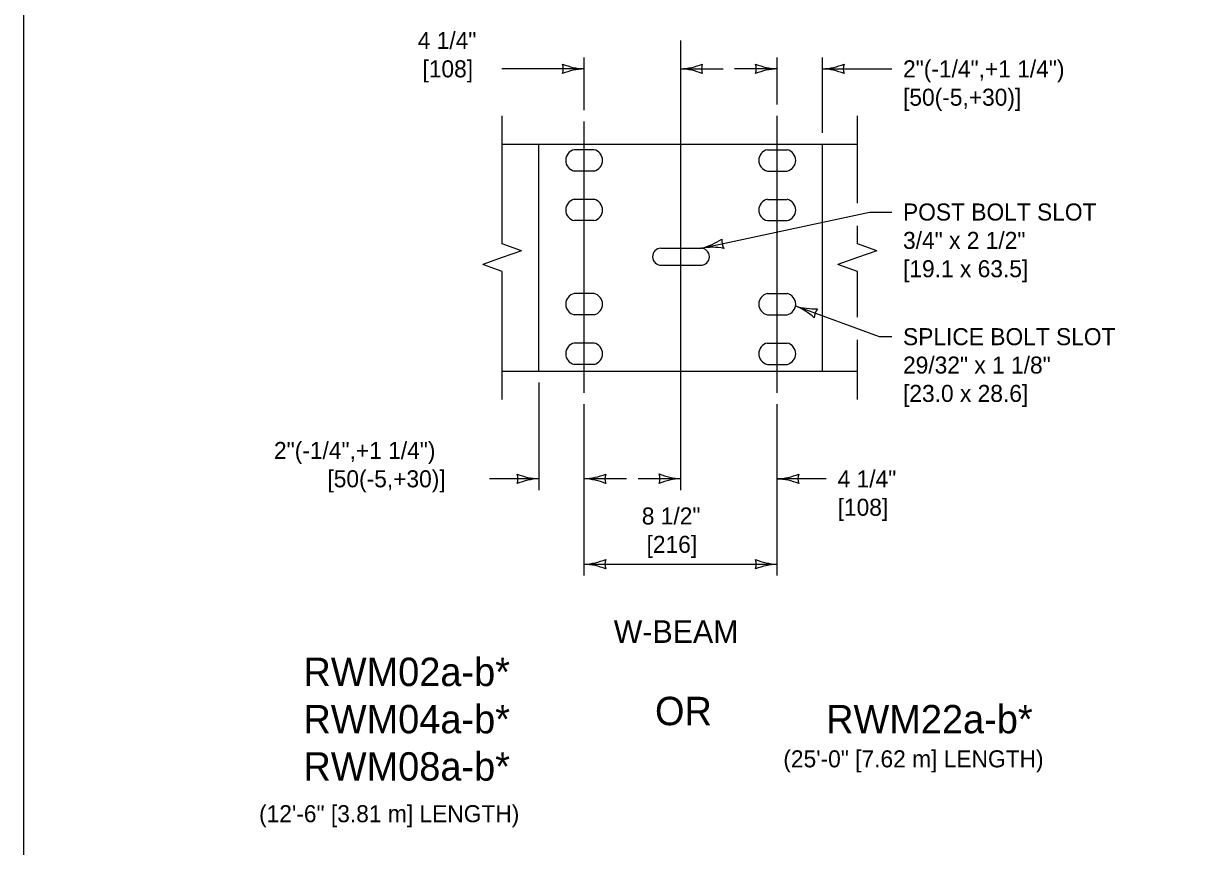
# Model space of a CAD drawing. Extents: x 49991.4 to 50021, y 49987.6 to 50011.4.
# Drawn here: x 50000.336 to 50004.482, y 50005.867 to 50008.768 of the extents above; entities that cross this region are included whole.
import ezdxf

# ---------------------------------------------------------------- set-up
doc = ezdxf.new("R2010")
doc.units = 0
for name, color, linetype in [('Level 1', 7, 'Continuous'), ('Level 2', 7, 'Continuous'), ('Level 3', 7, 'Continuous'), ('Level 4', 7, 'Continuous'), ('Level 5', 7, 'Continuous'), ('Level 6', 7, 'Continuous')]:
    doc.layers.add(name, color=color, linetype=linetype)

msp = doc.modelspace()

# ---------------------------------------------------------------- linework, layer by layer
at = {"layer": 'Level 1'}
for p, q in [((50002.0237, 50008.3428), (50003.2762, 50008.3428)), ((50002.1524, 50007.5428), (50002.1524, 50008.3428)), ((50002.3472, 50008.3231), (50002.2776, 50008.3231)), ((50002.9587, 50008.3231), (50003.0283, 50008.3231)), ((50002.3473, 50008.248), (50002.2775, 50008.248)), ((50002.9587, 50008.248), (50003.0284, 50008.248)), ((50002.3473, 50008.1482), (50002.2775, 50008.1482)), ((50002.9586, 50008.1482), (50003.0284, 50008.1482)), ((50002.3472, 50008.0731), (50002.2776, 50008.0731)), ((50002.9588, 50008.0731), (50003.0283, 50008.0731)), ((50002.5832, 50007.976), (50002.724, 50007.976)), ((50002.584, 50007.916), (50002.724, 50007.916)), ((50002.3475, 50007.8163), (50002.2773, 50007.8163)), ((50002.9584, 50007.8163), (50003.0287, 50007.8163)), ((50002.3473, 50007.7413), (50002.2775, 50007.7413)), ((50002.9586, 50007.7413), (50003.0285, 50007.7413)), ((50002.3475, 50007.6415), (50002.2773, 50007.6415)), ((50002.9584, 50007.6415), (50003.0287, 50007.6415)), ((50002.0237, 50007.5428), (50003.2762, 50007.5428)), ((50002.3473, 50007.5665), (50002.2775, 50007.5665)), ((50002.9586, 50007.5665), (50003.0285, 50007.5665))]:
    msp.add_line(p, q, dxfattribs=at)
msp.add_lwpolyline([(50008.6146, 50011.2628), (50000.3356, 50011.2628), (50000.3356, 50000.0624), (50008.6146, 50000.0624)], close=True, dxfattribs=at)
for centre, radius, start, end in [((50002.2859, 50008.2855), 0.0385, 102.4416, 257.4512), ((50002.3389, 50008.2855), 0.0385, 282.5457, 77.5615), ((50002.967, 50008.2855), 0.0385, 102.4385, 257.4543), ((50003.02, 50008.2855), 0.0385, 282.5488, 77.5584), ((50002.2859, 50008.1107), 0.0385, 102.5792, 257.5891), ((50002.3389, 50008.1107), 0.0385, 282.4077, 77.424), ((50002.967, 50008.1107), 0.0385, 102.576, 257.5923), ((50003.02, 50008.1107), 0.0385, 282.4109, 77.4208), ((50002.584, 50007.946), 0.03, 91.4333, 270.0049), ((50002.724, 50007.946), 0.03, 270.0024, 89.9976), ((50002.2859, 50007.7788), 0.0385, 102.9832, 257.3148), ((50002.3389, 50007.7788), 0.0385, 282.6821, 77.0198), ((50002.967, 50007.7788), 0.0385, 102.9802, 257.3179), ((50003.02, 50007.7788), 0.0385, 282.6852, 77.0168), ((50002.2859, 50007.604), 0.0385, 102.9832, 257.3148), ((50002.3389, 50007.604), 0.0385, 282.6821, 77.0198), ((50002.967, 50007.604), 0.0385, 102.9802, 257.3179), ((50003.02, 50007.604), 0.0385, 282.6852, 77.0168)]:
    msp.add_arc(centre, radius, start, end, dxfattribs=at)
at = {"layer": 'Level 3'}
for p, q in [((50002.3124, 50008.4631), (50002.3124, 50008.6483)), ((50002.993, 50008.4828), (50002.993, 50008.6483)), ((50003.153, 50008.3828), (50003.153, 50008.6483)), ((50002.3124, 50008.6083), (50002.0224, 50008.6083)), ((50002.653, 50008.6083), (50002.803, 50008.6083)), ((50002.993, 50008.6083), (50002.843, 50008.6083)), ((50003.153, 50008.6083), (50003.397, 50008.6083)), ((50002.7269, 50007.9759), (50003.3183, 50008.1036)), ((50003.3182, 50008.1036), (50003.397, 50008.1036)), ((50003.0579, 50007.7725), (50003.3533, 50007.6641)), ((50003.3533, 50007.6641), (50003.397, 50007.6641)), ((50002.1524, 50007.5028), (50002.1524, 50007.123)), ((50002.3124, 50006.8219), (50002.3124, 50007.4265)), ((50002.993, 50006.8219), (50002.993, 50007.4265)), ((50002.1524, 50007.163), (50001.979, 50007.163)), ((50002.4624, 50007.163), (50002.3124, 50007.163)), ((50002.653, 50007.1633), (50002.503, 50007.1633)), ((50003.1664, 50007.1627), (50002.993, 50007.1627)), ((50002.3124, 50006.8619), (50002.993, 50006.8619))]:
    msp.add_line(p, q, dxfattribs=at)
for centre, radius, start, end in [((50002.3216, 50008.8305), 0.2223, 247.456, 267.6395), ((50002.1842, 50008.6083), 0.0548, 342.1388, 17.8612), ((50002.6415, 50008.841), 0.233, 272.8273, 292.0772), ((50002.7812, 50008.6083), 0.0548, 162.1388, 197.8612), ((50003.0022, 50008.8305), 0.2223, 247.456, 267.6395), ((50002.8648, 50008.6083), 0.0548, 342.1388, 17.8612), ((50003.1415, 50008.841), 0.233, 272.8273, 292.0772), ((50003.2812, 50008.6083), 0.0548, 162.1388, 197.8612), ((50002.3239, 50008.3756), 0.233, 92.8273, 112.0772), ((50002.6438, 50008.3862), 0.2223, 67.456, 87.6395), ((50003.0045, 50008.3756), 0.233, 92.8273, 112.0772), ((50003.1438, 50008.3862), 0.2223, 67.456, 87.6395), ((50002.6666, 50008.2009), 0.233, 285.0166, 304.2665), ((50002.8523, 50008.0029), 0.0548, 174.3281, 210.0505), ((50002.7649, 50007.7568), 0.2223, 79.6453, 99.8288), ((50002.9728, 50007.5671), 0.2223, 47.3049, 67.4884), ((50003.1273, 50007.9949), 0.233, 252.6762, 271.9261), ((50003.1783, 50007.7283), 0.0548, 141.9877, 177.7101), ((50002.1616, 50007.3851), 0.2223, 247.456, 267.6395), ((50002.0242, 50007.163), 0.0548, 342.1388, 17.8612), ((50002.3009, 50007.3957), 0.233, 272.8273, 292.0772), ((50002.4406, 50007.163), 0.0548, 162.1388, 197.8612), ((50002.6622, 50007.3854), 0.2223, 247.456, 267.6395), ((50002.5248, 50007.1633), 0.0548, 342.1388, 17.8612), ((50002.9815, 50007.3954), 0.233, 272.8273, 292.0772), ((50003.1212, 50007.1627), 0.0548, 162.1388, 197.8612), ((50002.1639, 50006.9303), 0.233, 92.8273, 112.0772), ((50002.3032, 50006.9409), 0.2223, 67.456, 87.6395), ((50002.6645, 50006.9306), 0.233, 92.8273, 112.0772), ((50002.9838, 50006.9406), 0.2223, 67.456, 87.6395), ((50002.3009, 50007.0946), 0.233, 272.8273, 292.0772), ((50002.4406, 50006.8619), 0.0548, 162.1388, 197.8612), ((50003.0022, 50007.084), 0.2223, 247.456, 267.6395), ((50002.8648, 50006.8619), 0.0548, 342.1388, 17.8612), ((50002.3032, 50006.6398), 0.2223, 67.456, 87.6395), ((50003.0045, 50006.6292), 0.233, 92.8273, 112.0772)]:
    msp.add_arc(centre, radius, start, end, dxfattribs=at)
at = {"layer": 'Level 4'}
msp.add_line((50003.153, 50007.5428), (50003.153, 50008.3428), dxfattribs=at)
at = {"layer": 'Level 5'}
for p, q in [((50002.653, 50007.1233), (50002.653, 50008.7083)), ((50002.3124, 50007.4665), (50002.3124, 50008.4231)), ((50002.993, 50007.4665), (50002.993, 50008.4428))]:
    msp.add_line(p, q, dxfattribs=at)
at = {"layer": 'Level 6'}
for p, q in [((50002.0237, 50007.9914), (50002.0237, 50008.4428)), ((50003.2762, 50008.1345), (50003.2762, 50008.4428)), ((50003.2762, 50007.9914), (50003.2762, 50008.0545)), ((50002.0922, 50007.9671), (50002.0237, 50007.9914)), ((50002.0922, 50007.9671), (50002.0237, 50007.9428)), ((50003.3448, 50007.9671), (50003.2762, 50007.9914)), ((50003.3448, 50007.9671), (50003.2762, 50007.9428)), ((50002.0237, 50007.9428), (50001.9552, 50007.9185)), ((50002.0237, 50007.8942), (50001.9552, 50007.9185)), ((50003.2762, 50007.9428), (50003.2076, 50007.9185)), ((50003.2762, 50007.8942), (50003.2076, 50007.9185)), ((50002.0237, 50007.4428), (50002.0237, 50007.8942)), ((50003.2762, 50007.7324), (50003.2762, 50007.8942)), ((50003.2762, 50007.4428), (50003.2762, 50007.6524))]:
    msp.add_line(p, q, dxfattribs=at)

# ---------------------------------------------------------------- texts
at = {"layer": 'Level 2'}
for s, height, p in [('4 1/4"', 0.06, (50001.7256, 50008.6783)), ('[108]', 0.06, (50001.7424, 50008.5783)), ('2"(-1/4",+1 1/4")', 0.06, (50003.437, 50008.5783)), ('[50(-5,+30)]', 0.06, (50003.437, 50008.4783)), ('POST BOLT SLOT', 0.06, (50003.437, 50008.0736)), ('3/4" x 2 1/2"', 0.06, (50003.437, 50007.9736)), ('[19.1 x 63.5]', 0.06, (50003.437, 50007.8736)), ('SPLICE BOLT SLOT', 0.06, (50003.437, 50007.6341)), ('29/32" x 1 1/8"', 0.06, (50003.437, 50007.5341)), ('[23.0 x 28.6]', 0.06, (50003.437, 50007.4341)), ('2"(-1/4",+1 1/4")', 0.06, (50001.2188, 50007.233)), ('[50(-5,+30)]', 0.06, (50001.4072, 50007.133)), ('4 1/4"', 0.06, (50003.2064, 50007.1327)), ('[108]', 0.06, (50003.2064, 50007.0327)), ('8 1/2"', 0.06, (50002.5158, 50007.0019)), ('[216]', 0.06, (50002.5326, 50006.9019)), ('W-BEAM', 0.08, (50002.4169, 50006.5844)), ('RWM02a-b*', 0.1, (50001.3227, 50006.4323)), ('OR', 0.1, (50002.5624, 50006.2944)), ('RWM04a-b*', 0.1, (50001.3227, 50006.2657)), ('RWM22a-b*', 0.1, (50003.1658, 50006.2657)), ('RWM08a-b*', 0.1, (50001.3227, 50006.099)), ('(25\'-0" [7.62 m] LENGTH)', 0.06, (50003.0149, 50006.1457)), ('(12\'-6" [3.81 m] LENGTH)', 0.06, (50001.1662, 50005.9523))]:
    msp.add_text(s, height=height, dxfattribs=at).set_placement(p)

doc.saveas('drawing.dxf')
